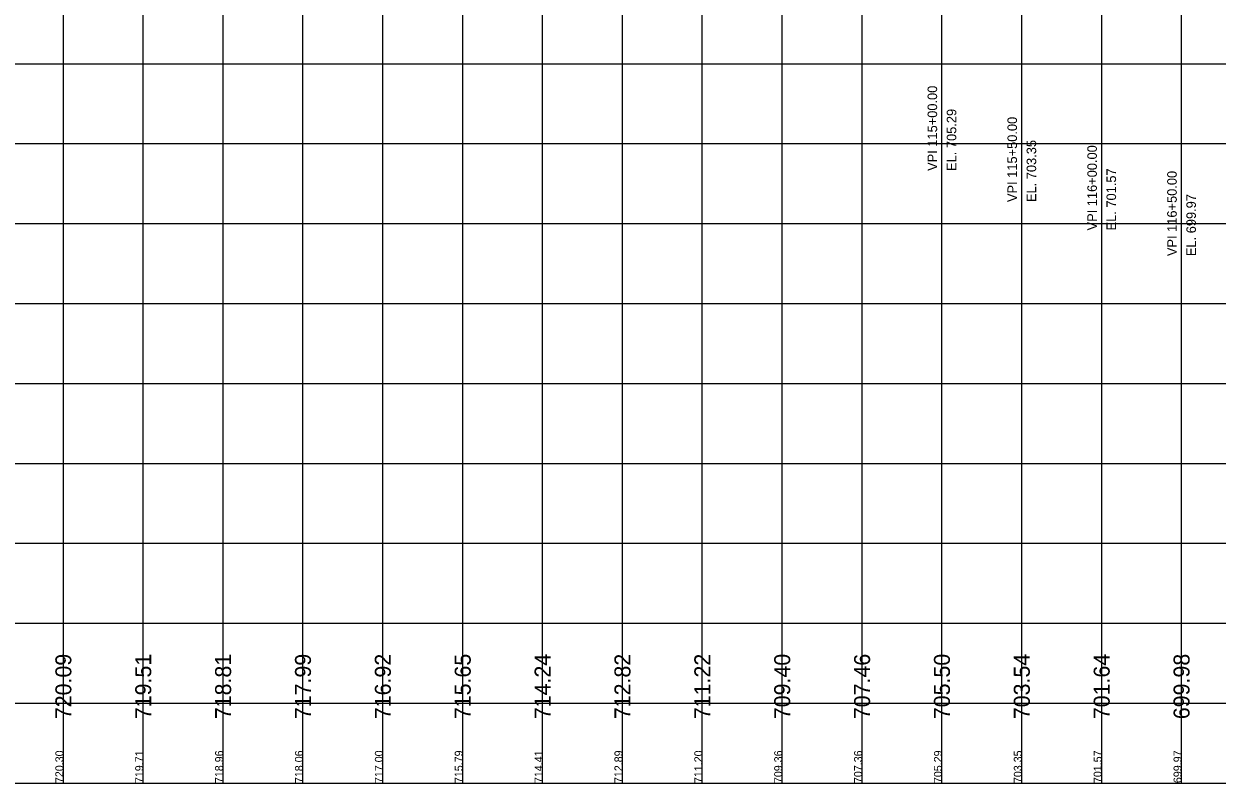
# Model space of a CAD drawing. Extents: x -7164 to 2214450, y -19642 to 253469.
# Drawn here: x 18125 to 18872, y -3000 to -2525 of the extents above; entities that cross this region are included whole.
import ezdxf

# ---------------------------------------------------------------- set-up
doc = ezdxf.new("R2010")
doc.units = 0
for name, color, linetype in [('DESIGN - PROFILE - Proposed Curve Text', 7, 'Continuous'), ('DESIGN - PROFILE - Proposed Text', 7, 'Continuous'), ('DESIGN - SCRATCH - User 1', 7, 'Continuous'), ('DESIGN - SHEET - Light Grid', 7, 'Continuous'), ('SURVEY - PROFILE - Ground Line with Text', 7, 'Continuous')]:
    doc.layers.add(name, color=color, linetype=linetype)

msp = doc.modelspace()

# ---------------------------------------------------------------- linework, layer by layer
at = {"layer": 'DESIGN - SCRATCH - User 1'}
msp.add_line((15000, -3000), (24100, -3000), dxfattribs=at)
msp.add_line((15000, -3000), (24100, -3000), dxfattribs=at)
at = {"layer": 'DESIGN - SHEET - Light Grid'}
for p, q in [((18150, -3000), (18150, -1000)), ((18150, -3000), (18150, -1000)), ((18200, -3000), (18200, -1000)), ((18200, -3000), (18200, -1000)), ((18250, -3000), (18250, -1000)), ((18250, -3000), (18250, -1000)), ((18300, -3000), (18300, -1000)), ((18300, -3000), (18300, -1000)), ((18350, -3000), (18350, -1000)), ((18350, -3000), (18350, -1000)), ((18400, -3000), (18400, -1000)), ((18400, -3000), (18400, -1000)), ((18450, -3000), (18450, -1000)), ((18450, -3000), (18450, -1000)), ((18500, -3000), (18500, -1000)), ((18500, -3000), (18500, -1000)), ((18550, -3000), (18550, -1000)), ((18550, -3000), (18550, -1000)), ((18600, -3000), (18600, -1000)), ((18600, -3000), (18600, -1000)), ((18650, -3000), (18650, -1000)), ((18650, -3000), (18650, -1000)), ((18700, -3000), (18700, -1000)), ((18700, -3000), (18700, -1000)), ((18750, -3000), (18750, -1000)), ((18750, -3000), (18750, -1000)), ((18800, -3000), (18800, -1000)), ((18800, -3000), (18800, -1000)), ((18850, -3000), (18850, -1000)), ((18850, -3000), (18850, -1000)), ((15000, -2550), (24100, -2550)), ((15000, -2550), (24100, -2550)), ((15000, -2600), (24100, -2600)), ((15000, -2600), (24100, -2600)), ((15000, -2650), (24100, -2650)), ((15000, -2650), (24100, -2650)), ((15000, -2700), (24100, -2700)), ((15000, -2700), (24100, -2700)), ((15000, -2750), (24100, -2750)), ((15000, -2750), (24100, -2750)), ((15000, -2800), (24100, -2800)), ((15000, -2800), (24100, -2800)), ((15000, -2850), (24100, -2850)), ((15000, -2850), (24100, -2850)), ((15000, -2900), (24100, -2900)), ((15000, -2900), (24100, -2900)), ((15000, -2950), (24100, -2950)), ((15000, -2950), (24100, -2950)), ((15000, -3000), (24100, -3000)), ((15000, -3000), (24100, -3000))]:
    msp.add_line(p, q, dxfattribs=at)

# ---------------------------------------------------------------- texts
at = {"layer": 'DESIGN - PROFILE - Proposed Curve Text'}
for s, p in [('VPI 115+00.00', (18697, -2617.06)), ('VPI 115+00.00', (18697, -2617.06)), ('EL. 705.29', (18709, -2617.06)), ('EL. 705.29', (18709, -2617.06)), ('VPI 115+50.00', (18747, -2636.53)), ('VPI 115+50.00', (18747, -2636.53)), ('EL. 703.35', (18759, -2636.53)), ('EL. 703.35', (18759, -2636.53)), ('VPI 116+00.00', (18797, -2654.29)), ('VPI 116+00.00', (18797, -2654.29)), ('EL. 701.57', (18809, -2654.29)), ('EL. 701.57', (18809, -2654.29)), ('VPI 116+50.00', (18847, -2670.35)), ('VPI 116+50.00', (18847, -2670.35)), ('EL. 699.97', (18859, -2670.35)), ('EL. 699.97', (18859, -2670.35))]:
    msp.add_text(s, height=6, rotation=90, dxfattribs=at).set_placement(p)
at = {"layer": 'DESIGN - PROFILE - Proposed Text'}
for s, p in [('720.30', (18150, -3000)), ('720.30', (18150, -3000)), ('719.71', (18200, -3000)), ('719.71', (18200, -3000)), ('718.96', (18250, -3000)), ('718.96', (18250, -3000)), ('718.06', (18300, -3000)), ('718.06', (18300, -3000)), ('717.00', (18350, -3000)), ('717.00', (18350, -3000)), ('715.79', (18400, -3000)), ('715.79', (18400, -3000)), ('714.41', (18450, -3000)), ('714.41', (18450, -3000)), ('712.89', (18500, -3000)), ('712.89', (18500, -3000)), ('711.20', (18550, -3000)), ('711.20', (18550, -3000)), ('709.36', (18600, -3000)), ('709.36', (18600, -3000)), ('707.36', (18650, -3000)), ('707.36', (18650, -3000)), ('705.29', (18700, -3000)), ('705.29', (18700, -3000)), ('703.35', (18750, -3000)), ('703.35', (18750, -3000)), ('701.57', (18800, -3000)), ('701.57', (18800, -3000)), ('699.97', (18850, -3000)), ('699.97', (18850, -3000))]:
    msp.add_text(s, height=5, rotation=90, dxfattribs=at).set_placement(p)
at = {"layer": 'SURVEY - PROFILE - Ground Line with Text'}
for s, p in [('720.09', (18155, -2960)), ('720.09', (18155, -2960)), ('719.51', (18205, -2960)), ('719.51', (18205, -2960)), ('718.81', (18255, -2960)), ('718.81', (18255, -2960)), ('717.99', (18305, -2960)), ('717.99', (18305, -2960)), ('716.92', (18355, -2960)), ('716.92', (18355, -2960)), ('715.65', (18405, -2960)), ('715.65', (18405, -2960)), ('714.24', (18455, -2960)), ('714.24', (18455, -2960)), ('712.82', (18505, -2960)), ('712.82', (18505, -2960)), ('711.22', (18555, -2960)), ('711.22', (18555, -2960)), ('709.40', (18605, -2960)), ('709.40', (18605, -2960)), ('707.46', (18655, -2960)), ('707.46', (18655, -2960)), ('705.50', (18705, -2960)), ('705.50', (18705, -2960)), ('703.54', (18755, -2960)), ('703.54', (18755, -2960)), ('701.64', (18805, -2960)), ('701.64', (18805, -2960)), ('699.98', (18855, -2960)), ('699.98', (18855, -2960))]:
    msp.add_text(s, height=10, rotation=90, dxfattribs=at).set_placement(p)

doc.saveas('drawing.dxf')
